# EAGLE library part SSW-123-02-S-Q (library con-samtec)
THROUGH-HOLE .025" SQ POST SOCKET Source: Samtec SSW.pdf
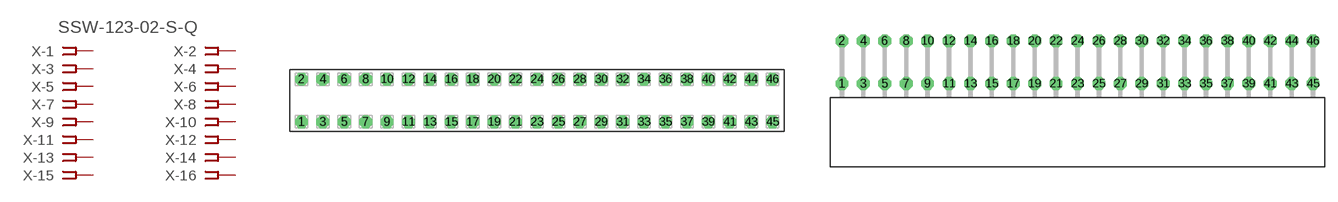
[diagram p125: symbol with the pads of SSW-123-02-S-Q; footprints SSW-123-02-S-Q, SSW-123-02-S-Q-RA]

Designator prefix X; gates -1=FPINV -2=FPIN -3=FPIN -4=FPIN -5=FPIN -6=FPIN -7=FPIN -8=FPIN -9=FPIN -10=FPIN -11=FPIN -12=FPIN -13=FPIN -14=FPIN -15=FPIN -16=FPIN -17=FPIN -18=FPIN -19=FPIN -20=FPIN -21=FPIN -22=FPIN -23=FPIN -24=FPIN -25=FPIN -26=FPIN -27=FPIN -28=FPIN -29=FPIN -30=FPIN -31=FPIN -32=FPIN -33=FPIN -34=FPIN -35=FPIN -36=FPIN -37=FPIN -38=FPIN -39=FPIN -40=FPIN -41=FPIN -42=FPIN -43=FPIN -44=FPIN -45=FPIN -46=FPIN

## SSW-123-02-S-Q (OC_FARNELL: unknown; OC_NEWARK: unknown)  [SSW-123-02-S-Q]
1  -1:1  pas
2  -2:1  pas
3  -3:1  pas
4  -4:1  pas
5  -5:1  pas
6  -6:1  pas
7  -7:1  pas
8  -8:1  pas
9  -9:1  pas
10  -10:1  pas
11  -11:1  pas
12  -12:1  pas
13  -13:1  pas
14  -14:1  pas
15  -15:1  pas
16  -16:1  pas
17  -17:1  pas
18  -18:1  pas
19  -19:1  pas
20  -20:1  pas
21  -21:1  pas
22  -22:1  pas
23  -23:1  pas
24  -24:1  pas
25  -25:1  pas
26  -26:1  pas
27  -27:1  pas
28  -28:1  pas
29  -29:1  pas
30  -30:1  pas
31  -31:1  pas
32  -32:1  pas
33  -33:1  pas
34  -34:1  pas
35  -35:1  pas
36  -36:1  pas
37  -37:1  pas
38  -38:1  pas
39  -39:1  pas
40  -40:1  pas
41  -41:1  pas
42  -42:1  pas
43  -43:1  pas
44  -44:1  pas
45  -45:1  pas
46  -46:1  pas

## SSW-123-02-S-QRA (OC_FARNELL: unknown; OC_NEWARK: unknown)  [SSW-123-02-S-Q-RA]
Pads as for SSW-123-02-S-Q

## Footprint SSW-123-02-S-Q (pad centres in mm)
THROUGH-HOLE .025" SQ POST SOCKET Source: Samtec SSW.pdf
drill 1 pad 1.5 octagon: 1 -27.94,-2.54; 2 -27.94,2.54; 3 -25.4,-2.54; 4 -25.4,2.54; 5 -22.86,-2.54; 6 -22.86,2.54; 7 -20.32,-2.54; 8 -20.32,2.54; 9 -17.78,-2.54; 10 -17.78,2.54; 11 -15.24,-2.54; 12 -15.24,2.54; 13 -12.7,-2.54; 14 -12.7,2.54; 15 -10.16,-2.54; 16 -10.16,2.54; 17 -7.62,-2.54; 18 -7.62,2.54; 19 -5.08,-2.54; 20 -5.08,2.54; 21 -2.54,-2.54; 22 -2.54,2.54; 23 0,-2.54; 24 0,2.54; 25 2.54,-2.54; 26 2.54,2.54; 27 5.08,-2.54; 28 5.08,2.54; 29 7.62,-2.54; 30 7.62,2.54; 31 10.16,-2.54; 32 10.16,2.54; 33 12.7,-2.54; 34 12.7,2.54; 35 15.24,-2.54; 36 15.24,2.54; 37 17.78,-2.54; 38 17.78,2.54; 39 20.32,-2.54; 40 20.32,2.54; 41 22.86,-2.54; 42 22.86,2.54; 43 25.4,-2.54; 44 25.4,2.54; 45 27.94,-2.54; 46 27.94,2.54

## Footprint SSW-123-02-S-Q-RA (pad centres in mm)
THROUGH-HOLE .025" SQ POST SOCKET Source: Samtec SSW.pdf
drill 1 pad 1.5 octagon: 1 -27.94,1.524; 2 -27.94,6.604; 3 -25.4,1.524; 4 -25.4,6.604; 5 -22.86,1.524; 6 -22.86,6.604; 7 -20.32,1.524; 8 -20.32,6.604; 9 -17.78,1.524; 10 -17.78,6.604; 11 -15.24,1.524; 12 -15.24,6.604; 13 -12.7,1.524; 14 -12.7,6.604; 15 -10.16,1.524; 16 -10.16,6.604; 17 -7.62,1.524; 18 -7.62,6.604; 19 -5.08,1.524; 20 -5.08,6.604; 21 -2.54,1.524; 22 -2.54,6.604; 23 0,1.524; 24 0,6.604; 25 2.54,1.524; 26 2.54,6.604; 27 5.08,1.524; 28 5.08,6.604; 29 7.62,1.524; 30 7.62,6.604; 31 10.16,1.524; 32 10.16,6.604; 33 12.7,1.524; 34 12.7,6.604; 35 15.24,1.524; 36 15.24,6.604; 37 17.78,1.524; 38 17.78,6.604; 39 20.32,1.524; 40 20.32,6.604; 41 22.86,1.524; 42 22.86,6.604; 43 25.4,1.524; 44 25.4,6.604; 45 27.94,1.524; 46 27.94,6.604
